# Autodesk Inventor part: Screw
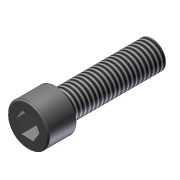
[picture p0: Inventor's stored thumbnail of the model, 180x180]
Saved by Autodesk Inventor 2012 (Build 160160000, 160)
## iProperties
Created: 2006-07
Part Number: Screw
Material: system_material_0
Description: SCREW, CAP, 1/4-20 X 3/8
Document SubType Name: Modeling
Designer: Z.MCGILL
Engineer: SAP
Manufacturer: Standard
Standards Organization: Custom
Mass: 26.2447 g
Surface Area: 18.9522 cm^2
Volume: 3.34682 cm^3
Density: 7.84168 g/cm^3
NetWeight: 0.005
WeightUOM: KG
ModelCode: Comp
Author: Z.MCGILL
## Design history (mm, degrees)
node "SHCS" dims "d23" = 0, "d24" = 0, "Head_Length" = 12.7, "Head_Chamfer" = 0.635, "Head_Diameter" = 19.05, "Thread_Length" = 44.45, "Hex_Head_Depth" = 9.525, "Hex_Head_Width" = 9.525, "Thread_Chamfer" = 0.2286, "Thread_Diameter" = 12.7, "ScaleForDerivedMember" = 10
body "Solid1"
feature "Solid1::SHCS" dims "d23" = 0, "d24" = 0, "Head_Length" = 12.7, "Head_Chamfer" = 0.635, "Head_Diameter" = 19.05, "Thread_Length" = 44.45, "Hex_Head_Depth" = 9.525, "Hex_Head_Width" = 9.525, "Thread_Chamfer" = 0.2286, "Thread_Diameter" = 12.7, "ScaleForDerivedMember" = 10
tag "TaggingFeature1"
